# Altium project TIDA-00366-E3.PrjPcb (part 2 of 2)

## Sheet TIDA-00366-E3_MCU Interface.SchDoc: MCU Interface
size 431 x 279 mm; Date: Not shown in title block; ApprovedBy: Not shown in title block; CheckedBy: Not shown in title block; Author: Not shown in title block; CompanyName: Not shown in title block; DrawnBy: NN; Engineer: Not shown in title block; Organization: Not shown in title block; Address1: Not shown in title block; Address2: Not shown in title block; Address3: Not shown in title block; Address4: Not shown in title block; DocumentNumber: 1; Revision: Use project parameter SCH_Rev; SheetNumber: 5; SheetTotal: 6; PageSetup: Record=PageOptions¦CenterHorizontal=True¦CenterVertical=True¦PrintScale=1.00¦XCorrection=1.00¦YCorrection=1.00¦PrintKind=0¦BorderSize=5000000¦LeftOffset=0¦BottomOffset=0¦Orientation=2¦PaperLength=1000¦PaperWidth=1000¦Scale=100¦PaperSource=15¦PrintQuality=600¦MediaType=1¦DitherType=10¦PaperKind=Letter¦PrintScaleMode=1
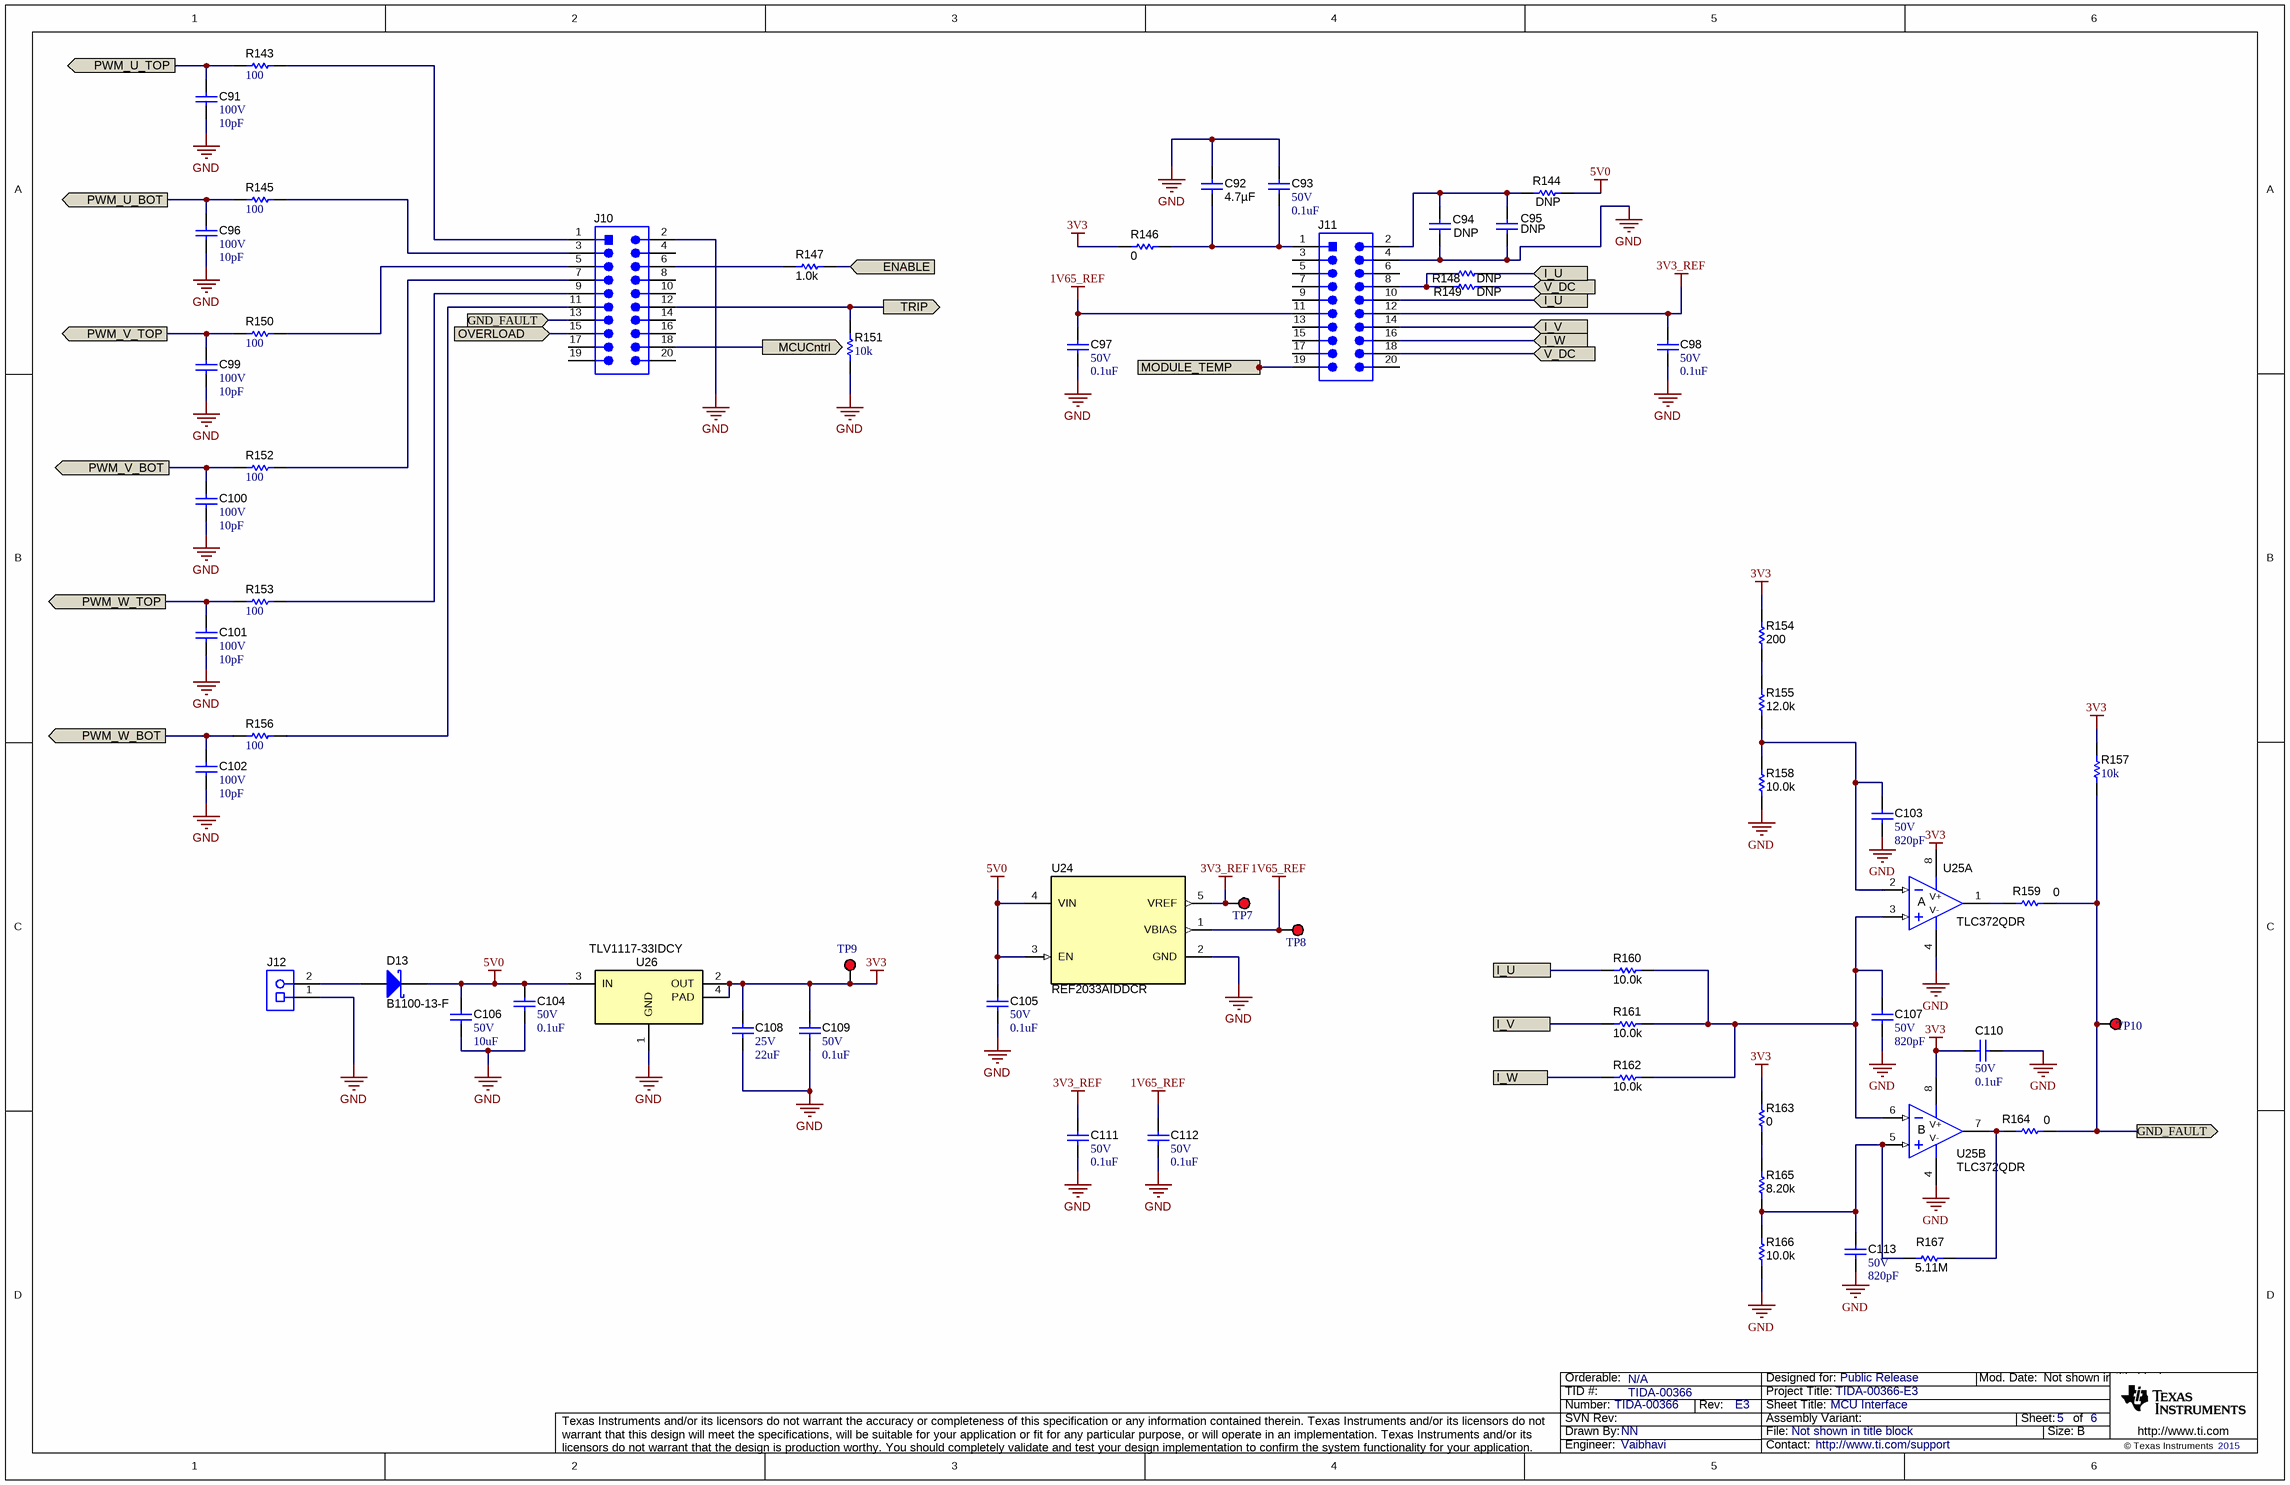
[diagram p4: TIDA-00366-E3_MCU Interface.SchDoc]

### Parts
C91  VDC_V: 100V  ValueDisplayed: 10pF  [0603]  (hidden comment: 885012006073)
C92  ValueDisplayed: 4.7µF  [0805_HV]  (hidden comment: C2012X5R1H475K125AB)
C93  VDC_V: 50V  ValueDisplayed: 0.1uF  [0603]  (hidden comment: GCM188R71H104KA57D)
C94  C2012X5R1H475K125AB  [0805_HV]  (value not drawn)
C95  C1608X7R1H104K  [0603]  (value not drawn)
C96  VDC_V: 100V  ValueDisplayed: 10pF  [0603]  (hidden comment: 885012006073)
C97  VDC_V: 50V  ValueDisplayed: 0.1uF  [0603]  (hidden comment: GCM188R71H104KA57D)
C98  VDC_V: 50V  ValueDisplayed: 0.1uF  [0603]  (hidden comment: GCM188R71H104KA57D)
C99  VDC_V: 100V  ValueDisplayed: 10pF  [0603]  (hidden comment: 885012006073)
C100  VDC_V: 100V  ValueDisplayed: 10pF  [0603]  (hidden comment: 885012006073)
C101  VDC_V: 100V  ValueDisplayed: 10pF  [0603]  (hidden comment: 885012006073)
C102  VDC_V: 100V  ValueDisplayed: 10pF  [0603]  (hidden comment: 885012006073)
C103  VDC_V: 50V  ValueDisplayed: 820pF  [0603]  (hidden comment: C0603C821K5RACTU)
C104  VDC_V: 50V  ValueDisplayed: 0.1uF  [0603]  (hidden comment: GCM188R71H104KA57D)
C105  VDC_V: 50V  ValueDisplayed: 0.1uF  [0603]  (hidden comment: GCM188R71H104KA57D)
C106  VDC_V: 50V  ValueDisplayed: 10uF  [1206_180]  (hidden comment: GRT31CR61H106KE01L)
C107  VDC_V: 50V  ValueDisplayed: 820pF  [0603]  (hidden comment: C0603C821K5RACTU)
C108  VDC_V: 25V  ValueDisplayed: 22uF  [0805_HV]  (hidden comment: CL21A226MAQNNNE)
C109  VDC_V: 50V  ValueDisplayed: 0.1uF  [0603]  (hidden comment: GCM188R71H104KA57D)
C110  VDC_V: 50V  ValueDisplayed: 0.1uF  [0603]  (hidden comment: GCM188R71H104KA57D)
C111  VDC_V: 50V  ValueDisplayed: 0.1uF  [0603]  (hidden comment: GCM188R71H104KA57D)
C112  VDC_V: 50V  ValueDisplayed: 0.1uF  [0603]  (hidden comment: GCM188R71H104KA57D)
C113  VDC_V: 50V  ValueDisplayed: 820pF  [0603]  (hidden comment: C0603C821K5RACTU)
D13  B1100-13-F  [SMA]
J10  TSW-110-07-G-D  [TSW-110-07-G-D]  (value not drawn)
J11  TSW-110-07-G-D  [TSW-110-07-G-D]  (value not drawn)
J12  282834-2  [TEC_282834-2]  (value not drawn)
R143  ValueDisplayed: 100  [0603]  (hidden comment: RC0603FR-07100RL)
R144  CRCW08050000Z0EA  [0805_HV]  (value not drawn)
R145  ValueDisplayed: 100  [0603]  (hidden comment: RC0603FR-07100RL)
R146  ValueDisplayed: 0  [0805_HV]  (hidden comment: CRCW08050000Z0EA)
R147  ValueDisplayed: 1.0k  [0603]  (hidden comment: RC0603JR-071KL)
R148  CRCW06030000Z0EA  [0603]  (value not drawn)
R149  CRCW06030000Z0EA  [0603]  (value not drawn)
R150  ValueDisplayed: 100  [0603]  (hidden comment: RC0603FR-07100RL)
R151  ValueDisplayed: 10k  [0603]  (hidden comment: RC0603JR-0710KL)
R152  ValueDisplayed: 100  [0603]  (hidden comment: RC0603FR-07100RL)
R153  ValueDisplayed: 100  [0603]  (hidden comment: RC0603FR-07100RL)
R154  ValueDisplayed: 200  [0603]  (hidden comment: RG1608P-201-B-T5)
R155  ValueDisplayed: 12.0k  [0603]  (hidden comment: RG1608P-123-B-T5)
R156  ValueDisplayed: 100  [0603]  (hidden comment: RC0603FR-07100RL)
R157  ValueDisplayed: 10k  [0603]  (hidden comment: RC0603JR-0710KL)
R158  ValueDisplayed: 10.0k  [0603]  (hidden comment: PHT0603Y1002BGT200)
R159  ValueDisplayed: 0  [0603]  (hidden comment: RC0603JR-070RL)
R160  ValueDisplayed: 10.0k  [0603]  (hidden comment: PHT0603Y1002BGT200)
R161  ValueDisplayed: 10.0k  [0603]  (hidden comment: PHT0603Y1002BGT200)
R162  ValueDisplayed: 10.0k  [0603]  (hidden comment: PHT0603Y1002BGT200)
R163  ValueDisplayed: 0  [0603]  (hidden comment: ERJ-3GEY0R00V)
R164  ValueDisplayed: 0  [0603]  (hidden comment: RC0603JR-070RL)
R165  ValueDisplayed: 8.20k  [0603]  (hidden comment: RG1608P-822-B-T5)
R166  ValueDisplayed: 10.0k  [0603]  (hidden comment: PHT0603Y1002BGT200)
R167  ValueDisplayed: 5.11M  [0603]  (hidden comment: CRCW06035M11FKEA)
TP7  5000  [Keystone5000]  (value not drawn)
TP8  5000  [Keystone5000]  (value not drawn)
TP9  5000  [Keystone5000]  (value not drawn)
TP10  5000  [Keystone5000]  (value not drawn)
U24  REF2033AIDDCR  [DDC0005A_N]
U25  TLC372QDR  [D0008A_N]  (parts A,B of 2)
U26  TLV1117-33IDCY  [DCY0003A_N]

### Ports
ENABLE (in), GND_FAULT (in), GND_FAULT (out), I_U, I_U (in), I_V, I_V (in), I_W, I_W (in), MCUCntrl (out), MODULE_TEMP (in), OVERLOAD (in), PWM_U_BOT (out), PWM_U_TOP (out), PWM_V_BOT (out), PWM_V_TOP (out), PWM_W_BOT (out), PWM_W_TOP (out), TRIP (out), V_DC (in)

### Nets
1V65_REF: C97.1 C112.1 J11.11 TP8.1 U24.1(VBIAS)
3V3: C108.1 C109.1 C110.1 R146.1 R154.1 R157.2 R163.1 TP9.1 U25.8(V+) U26.2(OUT) U26.4(PAD)  [project net VCCI]
3V3_REF: C98.1 C111.1 J11.12 TP7.1 U24.5(VREF)
5V0: C104.1 C105.1 C106.1 D13.1(K) R144.2 U24.3(EN) U24.4(VIN) U26.3(IN)
GND: C91.2 C92.1 C93.1 C94.2 C95.2 C96.2 C97.2 C98.2 C99.2 C100.2 C101.2 C102.2 C103.2 C104.2 C105.2 C106.2 C107.2 C108.2 C109.2 C110.2 C111.2 C112.2 C113.2 J10.2 J11.4 J12.1 R151.1 R158.2 R166.2 U24.2(GND) U25.4(V-) U26.1(GND)
ENABLE: R147.1 ; port ENABLE
GND_FAULT: J10.13 R157.1 R159.2 R164.2 TP10.1 ; port GND_FAULT
I_U: J11.10 R148.2 R160.1 ; port I_U
I_V: J11.14 R161.1 ; port I_V
I_W: J11.16 R162.1 ; port I_W
MCUCntrl: J10.18 ; port MCUCntrl
MODULE_TEMP: J11.19 ; port MODULE_TEMP
OVERLOAD: J10.15 ; port OVERLOAD
PWM_U_BOT: C96.1 R145.1 ; port PWM_U_BOT
PWM_U_TOP: C91.1 R143.1 ; port PWM_U_TOP
PWM_V_BOT: C100.1 R152.1 ; port PWM_V_BOT
PWM_V_TOP: C99.1 R150.1 ; port PWM_V_TOP
PWM_W_BOT: C102.1 R156.1 ; port PWM_W_BOT
PWM_W_TOP: C101.1 R153.1 ; port PWM_W_TOP
TRIP: J10.12 R151.2 ; port TRIP
V_DC: J11.18 R149.2 ; port V_DC
NetC92_2: C92.2 C93.2 J11.1 R146.2
NetC94_1: C94.1 C95.1 J11.2 R144.1
NetC103_1: C103.1 R155.2 R158.1 U25.2(IN-)
NetC107_1: C107.1 R160.2 R161.2 R162.2 U25.3(IN+) U25.6(IN-)
NetC113_1: C113.1 R165.2 R166.1 R167.1 U25.5(IN+)
NetD13_2: D13.2(A) J12.2
NetJ10_1: J10.1 R143.2
NetJ10_3: J10.3 R145.2
NetJ10_5: J10.5 R150.2
NetJ10_6: J10.6 R147.2
NetJ10_7: J10.7 R152.2
NetJ10_9: J10.9 R153.2
NetJ10_11: J10.11 R156.2
NetJ11_8: J11.8 R148.1 R149.1
NetR154_2: R154.2 R155.1
NetR159_1: R159.1 U25.1(OUT)
NetR163_2: R163.2 R165.1
NetR164_1: R164.1 R167.2 U25.7(OUT)

Not connected (* = marked no-connect by the designer): J10 4 8 10 14 16 17 19 20; J11 3 5 6 7 9 13 15 17 20

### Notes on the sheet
- Labels drawn without touching a wire or pin: 3V3

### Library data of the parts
C91 C96 C99-C102 = CMP-0078152-1: CAP, CERM, 10 pF, 100 V,+/- 5%, C0G/NP0, 0603; Manufacturer: Wurth Elektronik; TaMin_C: -55°C; Polarized: N; SizeAreaWB_mm2: 4.68; U/M: EA; Value: 10pF; TaMax_C: 125°C; SizeZ_mm: 1; SizeX_mm: 1.6; SizeY_mm: 0.8; SizeArea_mm2: 1.28; AEC Category: Q200
C92 = C2012X5R1H475K125AB: CAP, CERM, 4.7 µF, 50 V, +/- 10%, X5R, 0805; Manufacturer: TDK; Polarized: N; CompType: Capacitor; Value: 4.7uF; U/M: EA; Cap_F: 0.0000047; Tolerance_%: 10; Value1: Unknown; VDC_V: 50; Value2: 50V; TaMin_C: -55; TaMax_C: 85; Cap_Case: 0805; AEC Category: Q200
C93 C97 C98 C104 C105 C109-C112 = CMP-0007144-4: CAP, CERM, 0.1 uF, 50 V, +/- 10%, X7R, 0603; Manufacturer: MuRata; TaMin_C: -55°C; ESR_ohm: 0.02; Polarized: N; SizeAreaWB_mm2: 4.68; Value1: 0.02 ohm; U/M: EA; Value: 0.1uF; TaMax_C: 125°C; SizeZ_mm: 1; SizeX_mm: 1.6; SizeY_mm: 0.8; SizeArea_mm2: 1.28; Cap_F: 100nF; IRMS_A: 1.84A; AEC Category: Q200
C94 = C2012X5R1H475K125AB: CAP, CERM, 4.7 µF, 50 V, +/- 10%, X5R, 0805; Manufacturer: TDK; Polarized: N; CompType: Capacitor; Value: 4.7uF; ValueDisplayed: 4.7µF; U/M: EA; Cap_F: 0.0000047; Tolerance_%: 10; Value1: Unknown; VDC_V: 50; Value2: 50V; TaMin_C: -55; TaMax_C: 85; Cap_Case: 0805; AEC Category: Q200
C95 = C1608X7R1H104K: CAP, CERM, 0.1 µF, 50 V, +/- 10%, X7R, 0603; Manufacturer: TDK; Polarized: N; CompType: Capacitor; Value: 0.1uF; ValueDisplayed: 0.1µF; U/M: EA; Cap_F: 0.0000001; Tolerance_%: 10; ESR_ohm: 0.017; Value1: 0.017 ohm; VDC_V: 50; Value2: 50V; TaMin_C: -55; TaMax_C: 125; AEC Category: Q200
C103 C107 C113 = CMP-0006972-5: CAP, CERM, 820 pF, 50 V, +/- 10%, X7R, 0603; Manufacturer: Kemet; TaMin_C: -55°C; Polarized: N; SizeAreaWB_mm2: 4.68; Value1: Unknown; U/M: EA; Value: 820pF; TaMax_C: 125°C; SizeZ_mm: 1; SizeX_mm: 1.6; SizeY_mm: 0.8; SizeArea_mm2: 1.28; AEC Category: Q200
C106 = CMP-0009015-2: CAP, CERM, 10 uF, 50 V, +/- 10%, X5R, AEC-Q200 Grade 1, 1206; Manufacturer: MuRata; TaMin_C: -55°C; Polarized: N; SizeAreaWB_mm2: 10.92; Value1: Unknown; U/M: EA; Value: 10uF; TaMax_C: 85°C; SizeZ_mm: 1.8; SizeX_mm: 3.2; SizeY_mm: 1.6; Cap_Case: 1206; SizeArea_mm2: 5.12; AEC Qualified: Y; Cap_F: 10µF; AEC Grade: 1; AEC Category: Q200
C108 = CMP-0007990-2: CAP, CERM, 22 uF, 25 V, +/- 20%, X5R, 0805; Manufacturer: Samsung Electro-Mechanics; TaMin_C: -55°C; Polarized: N; SizeAreaWB_mm2: 6.75; Value1: Unknown; U/M: EA; Value: 22uF; TaMax_C: 85°C; SizeZ_mm: 1.45; SizeX_mm: 2; SizeY_mm: 1.25; Cap_Case: 0805; SizeArea_mm2: 2.5; Cap_F: 22µF; AEC Category: Q200
D13 = B1100-13-F: Diode, Schottky, 100 V, 1 A, SMA; Manufacturer: Diodes Inc.; U/M: EA; Vf_V: 0.79; Value: 100V; Value1: 1A; Value2: 0.79V; Io_A: 1; Vr_V: 100; TJmax_C: 150; RJC_CperW: 25; AEC Category: Q101
J10 J11 = TSW-110-07-G-D: Header, 100mil, 10x2, Gold, TH; Manufacturer: Samtec; SymbolCreator: a0412235; Pitch_mm: 2.54; Gender: Male; Shrouded: N; Row_Count: 2; Current_A: 6.3; Voltage_V: 550; Cert_CSA: Y
J12 = 282834-2: Terminal Block, 2x1, 2.54mm, TH; Manufacturer: TE Connectivity; SymbolCreator: a0412235
R143 R145 R150 R152 R153 R156 = CMP-0022736-4: RES, 100, 1%, 0.1 W, 0603; Manufacturer: Yageo; Power_W: 100mW; TempCo: 100 ppm/C; Value_Code: 100R; Value: 100; EIA_Code: E96; SizeX_mm: 1.6; SizeY_mm: 0.8; SizeZ_mm: 1; Value2: 0.1W; SizeArea_mm2: 1.28; AEC Qualified: N; VDC_V: 75V; AEC Category: Q200; SizeAreaWB_mm2: 4.68
R144 R146 = CRCW08050000Z0EA: RES, 0, 5%, 0.125 W, 0805; Manufacturer: Vishay-Dale; CompType: Resistor; Value: 0; Value_Code: 0000; Tolerance_%: 5; Power_W: 0.125; Value2: 0.125W; VDC_V: 150; TempCo: 200 ppm/C; EIA_Code: E24; U/M: EA; AEC Category: Q200
R147 = RC0603JR-071KL: RES, 1.0 k, 5%, 0.1 W, 0603; Manufacturer: Yageo America; CompType: Resistor; Value: 1.0k; Res_ohm: 1000; Value_Code: 1k00; Tolerance_%: 5; Power_W: 0.1; Value2: 0.1W; VDC_V: 50; TempCo: 100 ppm/C; EIA_Code: E24; U/M: EA; SizeArea_mm2: 1.28; SizeX_mm: 1.6; SizeY_mm: 0.8; SizeZ_mm: 1; AEC Category: Q200
R148 R149 = CRCW06030000Z0EA: RES, 0, 5%, 0.1 W, 0603; Manufacturer: Vishay-Dale; CompType: Resistor; Value: 0; Value_Code: 0000; Tolerance_%: 5; Power_W: 0.1; Value2: 0.1W; VDC_V: 75; TempCo: 200 ppm/C; EIA_Code: E24; U/M: EA; AEC Category: Q200
R151 R157 = CMP-0025886-5: RES, 10 k, 5%, 0.1 W, 0603; Manufacturer: Yageo; Power_W: 100mW; TempCo: 100 ppm/C; Value_Code: 10k0; Value: 10k; EIA_Code: E24; SizeX_mm: 1.6; SizeY_mm: 0.8; SizeZ_mm: 1; Value2: 0.1W; SizeArea_mm2: 1.28; AEC Qualified: N; VDC_V: 75V; AEC Category: Q200; SizeAreaWB_mm2: 4.68
R154 = RG1608P-201-B-T5: RES, 200, 0.1%, 0.1 W, 0603; Manufacturer: Susumu Co Ltd; CompType: Resistor; Value: 200; Value_Code: 200R; Tolerance_%: 0.1; Value2: 0.1W; VDC_V: 75; TempCo: 25 ppm/C; EIA_Code: E192; U/M: EA; SizeArea_mm2: 1.28; SizeX_mm: 1.6; SizeY_mm: 0.8; SizeZ_mm: 1; AEC Category: Q200
R155 = RG1608P-123-B-T5: RES, 12.0 k, 0.1%, 0.1 W, 0603; Manufacturer: Susumu Co Ltd; CompType: Resistor; Value: 12.0k; Res_ohm: 12000; Value_Code: 12k0; Tolerance_%: 0.1; Value2: 0.1W; VDC_V: 75; TempCo: 25 ppm/C; EIA_Code: E192; U/M: EA; AEC Category: Q200; SizeArea_mm2: 1.28; SizeX_mm: 1.6; SizeY_mm: 0.8; SizeZ_mm: 1
R158 = PHT0603Y1002BGT200: RES, 10.0 k, 0.1%, 0.0375 W, 0603; Manufacturer: Vishay Sfernice; CompType: Resistor; Value: 10.0k; Res_ohm: 10000; Value_Code: 10k0; Tolerance_%: 0.1; Power_W: 0.0375; VDC_V: 75; TempCo: 15 ppm/C; EIA_Code: E192; U/M: EA; AEC Category: Q200; SizeArea_mm2: 1.28; SizeX_mm: 1.6; SizeY_mm: 0.8; SizeZ_mm: 1
R159 R164 = RC0603JR-070RL: RES, 0, 5%, 0.1 W, 0603; Manufacturer: Yageo America; CompType: Resistor; Value: 0; Value_Code: 0000; Tolerance_%: 5; Power_W: 0.1; Value2: 0.1W; VDC_V: 50; TempCo: 200 ppm/C; EIA_Code: E24; U/M: EA
R160-R162 R166 = PHT0603Y1002BGT200: RES, 10.0 k, 0.1%, 0.0375 W, 0603; Manufacturer: Vishay Sfernice; CompType: Resistor; Value: 10.0k; Res_ohm: 10000; Value_Code: 10k0; Tolerance_%: 0.1; Power_W: 0.0375; VDC_V: 75; TempCo: 15 ppm/C; EIA_Code: E192; U/M: EA; AEC Category: Q200
R163 = ERJ-3GEY0R00V: RES, 0, 5%, 0.1 W, 0603; Manufacturer: Panasonic; CompType: Resistor; Value: 0; Value_Code: 0000; Tolerance_%: 5; Power_W: 0.1; Value2: 0.1W; VDC_V: 50; TempCo: 600 ppm/C; EIA_Code: E24; U/M: EA
R165 = RG1608P-822-B-T5: RES, 8.20 k, 0.1%, 0.1 W, 0603; Manufacturer: Susumu Co Ltd; CompType: Resistor; Value: 8.20k; Res_ohm: 8200; Value_Code: 8k20; Tolerance_%: 0.1; Value2: 0.1W; VDC_V: 75; TempCo: 25 ppm/C; U/M: EA; AEC Category: Q200; SizeArea_mm2: 1.28; SizeX_mm: 1.6; SizeY_mm: 0.8; SizeZ_mm: 1
R167 = CRCW06035M11FKEA: RES, 5.11 M, 1%, 0.1 W, 0603; Manufacturer: Vishay-Dale; CompType: Resistor; Value: 5.11Meg; Res_ohm: 5110000; Value_Code: 5M11; Tolerance_%: 1; Power_W: 0.1; Value2: 0.1W; VDC_V: 75; TempCo: 100 ppm/C; EIA_Code: E96; U/M: EA
TP7-TP10 = 5000: Test Point, Miniature, Red, TH; Manufacturer: Keystone; CompType: Test Point Loop; ContactFinish: Silver
U24 = REF2033AIDDCR: Low-Drift, Low-Power, Dual-Output, VREF and VREF / 2 Voltage References, DDC0005A; Alternate PartNumber: REF2033AIDDCT; Manufacturer: Texas Instruments; SymbolCreator: a0799628; CompType: IC; U/M: EA
U25 = TLC372QDR: LinCMOS Dual Differential Comparators, D0008A; Manufacturer: Texas Instruments; SymbolCreator: a0411947; CompType: IC; U/M: EA
U26 = TLV1117-33IDCY: FIXED LOW-DROPOUT VOLTAGE REGULATOR, DCY0003A; Manufacturer: Texas Instruments; SymbolCreator: a0411947; CompType: IC; U/M: EA

## Sheet TIDA-00366-E3_EVM_Hardware.SchDoc: Hardware
size 431 x 279 mm; Date: Not shown in title block; ApprovedBy: Not shown in title block; CheckedBy: Not shown in title block; Author: Not shown in title block; CompanyName: Not shown in title block; DrawnBy: NN; Engineer: Not shown in title block; Organization: Not shown in title block; Address1: Not shown in title block; Address2: Not shown in title block; Address3: Not shown in title block; Address4: Not shown in title block; DocumentNumber: 1; Revision: Use project parameter SCH_Rev; SheetNumber: 6; SheetTotal: 6; PageSetup: Record=PageOptions¦CenterHorizontal=True¦CenterVertical=True¦PrintScale=1.00¦XCorrection=1.00¦YCorrection=1.00¦PrintKind=0¦BorderSize=5000000¦LeftOffset=0¦BottomOffset=0¦Orientation=2¦PaperLength=1000¦PaperWidth=1000¦Scale=100¦PaperSource=15¦PrintQuality=600¦MediaType=1¦DitherType=10¦PaperKind=Letter¦PrintScaleMode=1
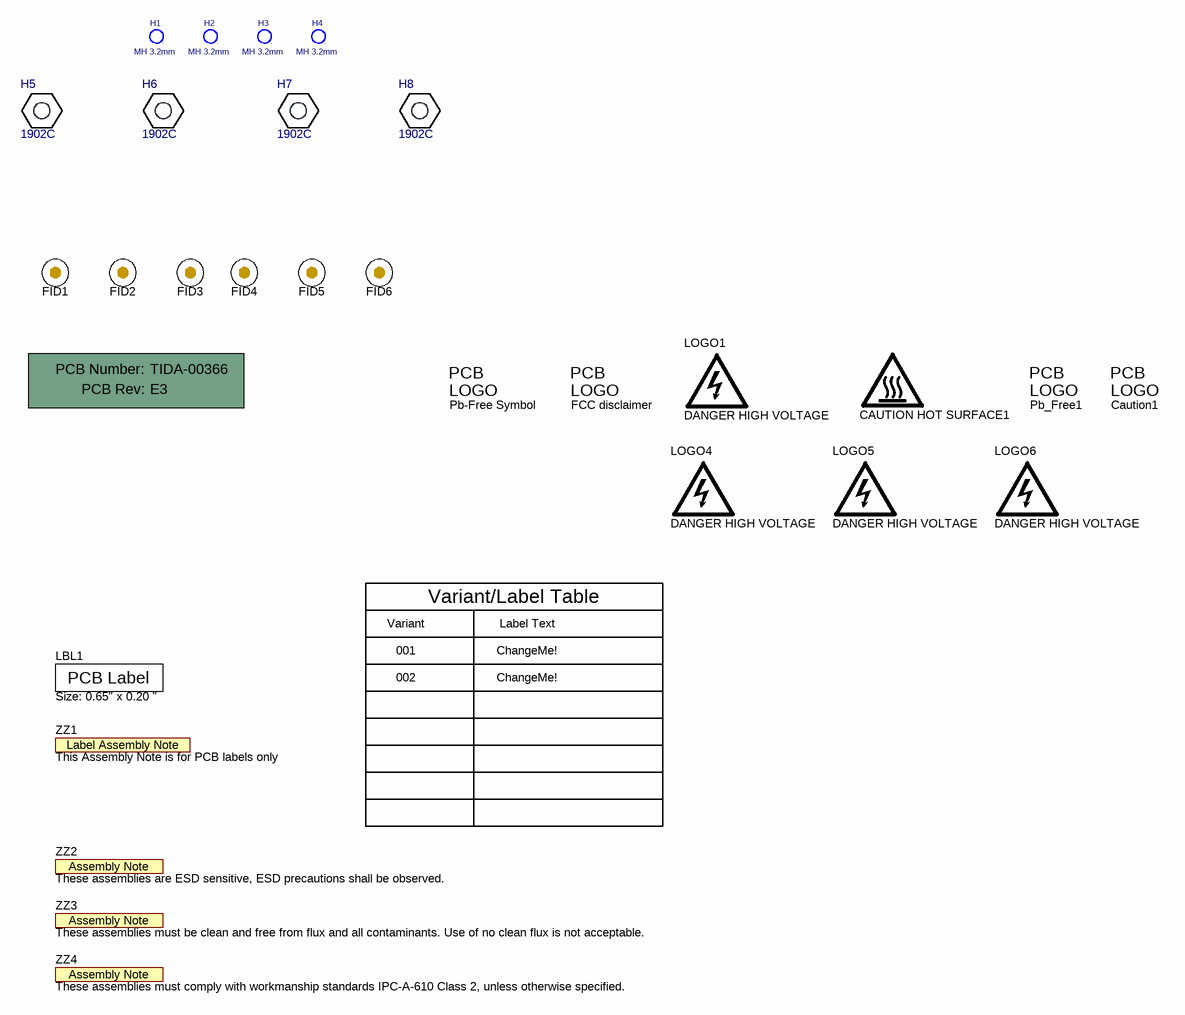
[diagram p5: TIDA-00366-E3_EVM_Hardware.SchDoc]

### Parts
!PCB1  Printed Circuit Board  (value not drawn)  (mechanical)
Caution1  CAUTION.  READ USER GUIDE BEFORE USE  [IEC_Caution_Medium]  (value not drawn)  (no BOM)
CAUTION_HOT_SURFACE1  CAUTION HOT SURFACE  [IEC_HotSurface_Medium]  (value not drawn)  (no BOM)
FID1  Fiducial  [Fiducial10-20]  (value not drawn)
FID2  Fiducial  [Fiducial10-20]  (value not drawn)
FID3  Fiducial  [Fiducial10-20]  (value not drawn)
FID4  Fiducial  [Fiducial10-20]  (value not drawn)
FID5  Fiducial  [Fiducial10-20]  (value not drawn)
FID6  Fiducial  [Fiducial10-20]  (value not drawn)
H1  MH 3.2mm  [MH3.2_H5_W6_KO8_STARHEAD]
H2  MH 3.2mm  [MH3.2_H5_W6_KO8_STARHEAD]
H3  MH 3.2mm  [MH3.2_H5_W6_KO8_STARHEAD]
H4  MH 3.2mm  [MH3.2_H5_W6_KO8_STARHEAD]
H5  1902C  [Keystone_1902C]
H6  1902C  [Keystone_1902C]
H7  1902C  [Keystone_1902C]
H8  1902C  [Keystone_1902C]
LBL1  Size: 0.65" x 0.20 "  [Label_650x200]
LOGO1  DANGER HIGH VOLTAGE  [IEC_HighVoltage_medium]  (no BOM)
Logo2  Pb-Free Symbol  [Pb-Free_Overlay_Small]  (no BOM)
Logo3  FCC disclaimer  [FCC_disclaimer]  (no BOM)
LOGO4  DANGER HIGH VOLTAGE  [IEC_HighVoltage_medium]  (no BOM)
LOGO5  DANGER HIGH VOLTAGE  [IEC_HighVoltage_medium]  (no BOM)
LOGO6  DANGER HIGH VOLTAGE  [IEC_HighVoltage_medium]  (no BOM)
Pb_Free1  ESD Susceptible  [ESD_Overlay_Medium]  (value not drawn)  (no BOM)
ZZ1  This Assembly Note is for PCB labels only  [AssemblyNoteLabel]  (no BOM)
ZZ2  These assemblies are ESD sensitive, ESD precautions shall be observed.  [AssemblyNote]  (no BOM)
ZZ3  These assemblies must be clean and free from flux and all contaminants. Use of no clean flux is not acceptable.  [AssemblyNote]  (no BOM)
ZZ4  These assemblies must comply with workmanship standards IPC-A-610 Class 2, unless otherwise specified.  [AssemblyNote]  (no BOM)

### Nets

Not connected (* = marked no-connect by the designer): H1 1; H2 1; H3 1; H4 1

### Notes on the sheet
- Variant
- Variant/Label Table
- Label Text
- 001
- 002
- ChangeMe!

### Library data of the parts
!PCB1 = PCB: Manufacturer: Any; PartNumber: TIDA-00366; SymbolCreator: a0412235
Caution1 = IEC_Caution: IEC 61010-1 Caution Warning; SymbolCreator: a0412235
CAUTION_HOT_SURFACE1 = IEC_HotSurface: IEC 61010-1 Hot Surface Warning; SymbolCreator: a0412235
FID1-FID6 = Fiducial: Fiducial mark.  There is nothing to buy or mount.; SymbolCreator: codlsc
H1-H4 = MH 3_0.5MM: Mountin hole, NPTH Drill 3.2mm
H5-H8 = CMP-0003610-1: Manufacturer: Keystone; CompType: Hardware
LBL1 = THT-14-423-10: Thermal Transfer Printable Labels, 0.650" W x 0.200" H - 10,000 per roll; Manufacturer: Brady; SymbolCreator: a0412235; CompType: Label
LOGO1 LOGO4-LOGO6 = IEC_HighVoltage: IEC 61010-1 High Voltage Warning; SymbolCreator: a0412235
Logo2 = Pb-Free: SymbolCreator: a0412235
Logo3 = FCC_disclaimer: SymbolCreator: codlsc
Pb_Free1 = ESD_Susceptible: ESD Susceptible Symbol; SymbolCreator: a0412235
ZZ1 = AssemblyNoteLabel: SymbolCreator: a0412235
ZZ2-ZZ4 = AssemblyNote: SymbolCreator: codlsc

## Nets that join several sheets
1V65_REF: TIDA-00366-E3_Current sense (6 pins), TIDA-00366-E3_DC BUS and TEMP Sense (C56.2 C66.2 R86.1 R99.1), TIDA-00366-E3_MCU Interface (5 pins)
GND: TIDA-00366-E3_Current sense (42 pins), TIDA-00366-E3_Gate driver and Module (18 pins), TIDA-00366-E3_DC BUS and TEMP Sense (18 pins), TIDA-00366-E3_MCU Interface (32 pins)
VCCI: TIDA-00366-E3_Current sense (28 pins), TIDA-00366-E3_Gate driver and Module (14 pins), TIDA-00366-E3_DC BUS and TEMP Sense (10 pins), TIDA-00366-E3_MCU Interface (11 pins)
5V_VDC: TIDA-00366-E3_Gate driver and Module (R129.1), TIDA-00366-E3_DC BUS and TEMP Sense (7 pins)
+16V_GPS: TIDA-00366-E3_Gate driver and Module (14 pins), TIDA-00366-E3_DC BUS and TEMP Sense (R67.1)
ENABLE: TIDA-00366-E3_Gate driver and Module (R110.1 R111.1 R127.1 U20.4), TIDA-00366-E3_MCU Interface (R147.1)
GND_FAULT: TIDA-00366-E3_Gate driver and Module (U21.1), TIDA-00366-E3_MCU Interface (5 pins)
I_U: TIDA-00366-E3_Current sense (C8.1 R5.2), TIDA-00366-E3_MCU Interface (J11.10 R148.2 R160.1)
I_V: TIDA-00366-E3_Current sense (C22.1 R26.2), TIDA-00366-E3_MCU Interface (J11.14 R161.1)
I_W: TIDA-00366-E3_Current sense (C36.1 R47.2), TIDA-00366-E3_MCU Interface (J11.16 R162.1)
MCUCntrl: TIDA-00366-E3_Gate driver and Module (U20.1), TIDA-00366-E3_MCU Interface (J10.18)
MODULE_TEMP: TIDA-00366-E3_DC BUS and TEMP Sense (C64.1 R92.2), TIDA-00366-E3_MCU Interface (J11.19)
NTC: TIDA-00366-E3_Gate driver and Module (R77.2 R129.2 U23.17), TIDA-00366-E3_DC BUS and TEMP Sense (R89.1)
OVERLOAD: TIDA-00366-E3_Current sense (7 pins), TIDA-00366-E3_Gate driver and Module (U21.6), TIDA-00366-E3_MCU Interface (J10.15)
PWM_U_BOT: TIDA-00366-E3_Gate driver and Module (U18.2), TIDA-00366-E3_MCU Interface (C96.1 R145.1)
PWM_U_TOP: TIDA-00366-E3_Gate driver and Module (U18.1), TIDA-00366-E3_MCU Interface (C91.1 R143.1)
PWM_V_BOT: TIDA-00366-E3_Gate driver and Module (U22.2), TIDA-00366-E3_MCU Interface (C100.1 R152.1)
PWM_V_TOP: TIDA-00366-E3_Gate driver and Module (U22.1), TIDA-00366-E3_MCU Interface (C99.1 R150.1)
PWM_W_BOT: TIDA-00366-E3_Gate driver and Module (U19.2), TIDA-00366-E3_MCU Interface (C102.1 R156.1)
PWM_W_TOP: TIDA-00366-E3_Gate driver and Module (U19.1), TIDA-00366-E3_MCU Interface (C101.1 R153.1)
TRIP: TIDA-00366-E3_Gate driver and Module (U21.3), TIDA-00366-E3_MCU Interface (J10.12 R151.2)
U_PHASE: TIDA-00366-E3_Current sense (R10.1), TIDA-00366-E3_Gate driver and Module (J4.1 R121.1)
U_TOP_REF: TIDA-00366-E3_Current sense (6 pins), TIDA-00366-E3_Gate driver and Module (10 pins)
V_DC: TIDA-00366-E3_DC BUS and TEMP Sense (C53.1 R78.2), TIDA-00366-E3_MCU Interface (J11.18 R149.2)
V_PHASE: TIDA-00366-E3_Current sense (R31.1), TIDA-00366-E3_Gate driver and Module (J5.1 R123.2)
V_TOP_REF: TIDA-00366-E3_Current sense (6 pins), TIDA-00366-E3_Gate driver and Module (10 pins)
VCC_U: TIDA-00366-E3_Current sense (R9.1), TIDA-00366-E3_Gate driver and Module (5 pins)
VCC_V: TIDA-00366-E3_Current sense (R30.1), TIDA-00366-E3_Gate driver and Module (5 pins)
VCC_W: TIDA-00366-E3_Current sense (R51.1), TIDA-00366-E3_Gate driver and Module (5 pins)
VDC+: TIDA-00366-E3_Gate driver and Module (8 pins), TIDA-00366-E3_DC BUS and TEMP Sense (D1.1 R65.2)
VDC-: TIDA-00366-E3_Gate driver and Module (12 pins), TIDA-00366-E3_DC BUS and TEMP Sense (15 pins)
W_PHASE: TIDA-00366-E3_Current sense (R52.1), TIDA-00366-E3_Gate driver and Module (J6.1 R124.2)
W_TOP_REF: TIDA-00366-E3_Current sense (6 pins), TIDA-00366-E3_Gate driver and Module (10 pins)

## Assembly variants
001: not fitted C12 C26 C40 C69 C70 C83 C94 C95 D1 D2 J1 J2 J3 R18 R21 R39 R42 R60 R63 R77 R86 R99 R144 R148 R149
